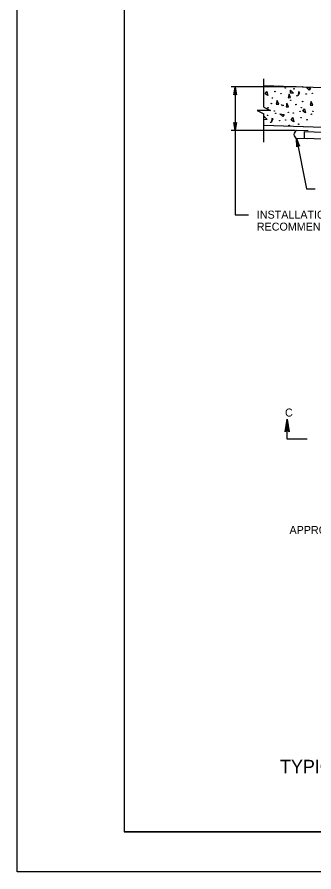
# Model space of a CAD drawing. Extents: x 2709 to 3899, y 22 to 1210.
# Drawn here: x 2708.9 to 2819.9, y 22.2 to 342.4 of the extents above; entities that cross this region are included whole.
import ezdxf

# ---------------------------------------------------------------- set-up
doc = ezdxf.new("R2010")
doc.units = 0
for name, color, linetype in [('1', 7, 'Continuous'), ('2', 7, 'Continuous'), ('3', 7, 'Continuous'), ('PLT-BNDY', 7, 'Continuous')]:
    doc.layers.add(name, color=color, linetype=linetype)

# ---------------------------------------------------------------- blocks, each defined once
blk = doc.blocks.new('RARROW')
at = {"layer": '3'}
blk.add_lwpolyline([(-2.2695, 0.285), (-2.184875, 0.12075), (0, 0), (-2.2695, 0.285), (-2.38575, 0.384625), (0, 0), (-2.183125, -0.108), (-2.262875, -0.2705), (0, 0), (-2.38575, -0.379125), (-2.262875, -0.2705)], dxfattribs=at)

msp = doc.modelspace()

# ---------------------------------------------------------------- linework, layer by layer
at = {"layer": '1'}
for p, q in [((2748.86, 601.17), (2748.86, 37.17)), ((3534.86, 37.17), (2748.86, 37.17)), ((2748.86, 37.17), (3334.86, 37.17))]:
    msp.add_line(p, q, dxfattribs=at)
at = {"layer": '2'}
for p, q in [((2801.15, 308.67), (2801.15, 319.29)), ((2813.28, 316.29), (2788.9, 316.29)), ((2790.4, 316.29), (2790.4, 299.92)), ((2801.15, 295.54), (2801.15, 306.17)), ((2812.9, 299.92), (2788.9, 299.92)), ((2790.4, 299.92), (2790.4, 268.29)), ((2817.78, 299.79), (2813.4, 299.92)), ((2816.4, 299.54), (3040.28, 291.92)), ((2816.4, 297.04), (2816.4, 299.54)), ((2817.4, 296.79), (2813.4, 296.92)), ((2813.4, 296.92), (2817.15, 278.04)), ((2816.4, 297.04), (3040.28, 289.42)), ((2817.15, 278.04), (2820.4, 278.04)), ((2790.4, 268.29), (2795.4, 268.29))]:
    msp.add_line(p, q, dxfattribs=at)
for points in [[(2801.15, 316.79), (2948.65, 311.79), (2948.65, 296.79), (2801.15, 301.79), (2801.15, 301.79)], [(2807.03, 316.29), (2806.53, 316.54)], [(2806.9, 316.54), (2807.03, 316.29)], [(2818.15, 315.04), (2817.03, 316.17)], [(2817.03, 316.17), (2818.65, 315.79)], [(2818.65, 315.79), (2818.15, 315.04)], [(2801.15, 308.67), (2803.65, 307.42), (2798.65, 307.42), (2801.15, 306.17)], [(2801.15, 303.92), (2801.28, 305.17)], [(2801.28, 305.17), (2802.4, 304.04)], [(2802.4, 304.04), (2801.15, 303.92)], [(2801.28, 302.29), (2801.15, 302.54)], [(2801.15, 302.29), (2801.28, 302.29)], [(2815.9, 301.29), (2815.9, 301.29)], [(2816.03, 301.29), (2815.9, 301.29)], [(2809.22, 187.29), (2809.6, 187.54), (2809.85, 191.79), (2809.22, 187.29), (2809.1, 187.04), (2809.85, 191.79), (2810.1, 187.54), (2810.35, 187.29), (2809.85, 191.79), (2810.6, 187.04), (2810.35, 187.29)], [(2817.35, 184.29), (2809.85, 184.29), (2809.85, 191.79)]]:
    msp.add_lwpolyline(points, dxfattribs=at)
for points in [[(2801.65, 313.67), (2802.28, 314.54), (2802.65, 313.04)], [(2811.15, 313.92), (2811.15, 315.04), (2812.28, 313.92)], [(2814.65, 314.17), (2814.15, 314.42), (2814.03, 313.04)], [(2806.15, 311.17), (2805.78, 309.79), (2806.78, 309.79)], [(2810.65, 313.54), (2810.28, 312.17), (2811.15, 312.29)], [(2818.9, 310.79), (2818.53, 309.42), (2819.53, 309.42)], [(2809.78, 310.17), (2809.53, 308.79), (2810.4, 308.79)], [(2815.78, 307.17), (2816.4, 308.04), (2816.78, 306.54)], [(2804.65, 304.29), (2804.15, 304.42), (2804.03, 303.04)], [(2808.78, 305.92), (2808.28, 305.17), (2807.15, 306.17)], [(2811.4, 303.79), (2812.03, 304.79), (2812.4, 303.17)]]:
    msp.add_lwpolyline(points, close=True, dxfattribs=at)
for centre in [(2802.33, 316.32), (2805.31, 314.52), (2809.15, 315.83), (2812.46, 315.55), (2815.56, 316.3), (2819.29, 313.83), (2804.38, 312.11), (2807.56, 313.75), (2811.23, 311.27), (2813.58, 312.95), (2815.67, 310.79), (2816.99, 313.58), (2802.74, 308.45), (2803.96, 310.04), (2807.78, 309.46), (2808.38, 309.33), (2813.15, 309.67), (2815.17, 308.48), (2802.53, 305.61), (2805.08, 307.23), (2805.63, 306.36), (2810.31, 306.72), (2812.13, 306.52), (2814.68, 307.13), (2815.11, 304.72), (2818.95, 306.04), (2819.51, 307.1), (2803.65, 303.01), (2807.05, 303.64), (2809.35, 303.89), (2810.63, 301.9), (2814.18, 302.31), (2817.36, 303.95)]:
    msp.add_circle(centre, 0.0919, dxfattribs=at)
msp.add_arc((2814.05, 298.42), 1.63, 113.3191, 246.6809, dxfattribs=at)
at = {"layer": 'PLT-BNDY'}
msp.add_lwpolyline([(2708.86, 616.17), (3549.86, 616.17), (3549.86, 22.17), (2708.86, 22.17)], close=True, dxfattribs=at)

# ---------------------------------------------------------------- block references
at = {"layer": '2'}
for p, xscale, yscale, rotation in [((2790.4, 316.29), 1.2574347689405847, 1.3092961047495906, 89.99999999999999), ((2790.4, 299.92), 1.2574347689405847, 1.3092961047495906, -90.00000000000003), ((2813.4, 296.92), 1.2574347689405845, 1.3092961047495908, 101.17108904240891)]:
    msp.add_blockref('RARROW', p, dxfattribs=dict(at, xscale=xscale, yscale=yscale, rotation=rotation))

# ---------------------------------------------------------------- texts
for s, height, p in [('INSTALLATION DEPTH AS', 3, (2798.53, 266.92)), ('RECOMMENDED BY MANUFACTURER.', 3, (2798.53, 262.42)), ('APPROX. 3"', 3, (2810.75, 148.77)), ('TYPICAL SENSOR INSTALLATION - MAGNETOMETER DETECTOR', 5, (2807.23, 59.16))]:
    msp.add_text(s, height=height, dxfattribs=at).set_placement(p)
msp.add_text('C', height=3, rotation=5, dxfattribs=at).set_placement((2809.21, 192.63))

doc.saveas('drawing.dxf')
